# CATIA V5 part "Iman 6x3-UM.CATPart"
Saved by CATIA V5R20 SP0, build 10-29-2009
Part number: Iman 6x3-UM
Revision: ANY
Definition: UNKNOWN
Nomenclature: Iman 6x3-UM
Source: Unknown
Bounding box of the stored display mesh (mm): x -3 to 3, y -2.853 to 2.853, z 0 to 3
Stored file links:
  C:\Users\Utente\Desktop\IO LAVORO\3D X SITO CF\X SITO\3D files UM\UM043642 PRODUCT\Iman 6x3-UM.CATPart
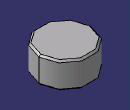
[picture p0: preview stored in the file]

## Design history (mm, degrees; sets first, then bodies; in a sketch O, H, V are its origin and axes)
Body1 "Chaflán1" (main body)
  Solid1: solid without history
